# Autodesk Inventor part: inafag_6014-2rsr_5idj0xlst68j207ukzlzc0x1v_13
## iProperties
Shininess: 64.0
Angle Display Precision: 2
Document Length Units: 11269
Document Angle Units: 11279
Document Time Units: 11290
Document Mass Units: 11283
Document Length Units Precision: 3
Document Angle Units Precision: 2
Compacted: True
Created: 2008-08
Part Number: inafag_6014-2rsr_5idj0xlst68j207ukzlzc0x1v_13
Document SubType Name: Modeling
Designer: tpomodeler
Density: 0.0
Volumn: 0.0
Area: 0.0
PropertySet Name: Model Information
Control State: 0
Master: False
Checked Out: False
Author: tpomodeler
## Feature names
1. inafag_6014-2rsr_5idj0xlst68j207ukzlzc0x1v
